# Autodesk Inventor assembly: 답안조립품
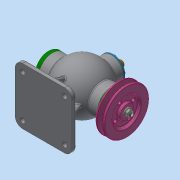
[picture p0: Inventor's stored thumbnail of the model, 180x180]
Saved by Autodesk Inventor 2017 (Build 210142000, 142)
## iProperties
Part Number: 답안조립품
Material: 일반
Document SubType Name: Assembly
Designer: MRC
Author: MRC
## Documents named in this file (16)
- C:\Users\MRC\Desktop\720811V1001\답안조립품.iam
- C:\Users\MRC\Desktop\720811V1001\본체.ipt
- C:\Users\MRC\Desktop\720811V1001\V-벨트풀리.ipt
- C:\Users\MRC\Desktop\720811V1001\너트 M8.ipt
- C:\Users\MRC\Desktop\720811V1001\뒤커버.ipt
- C:\Users\MRC\Desktop\720811V1001\베어링- 6202.ipt
- KS B 2023 - 6202 - 15 x 35 x 11 - 7.8.ipt
- C:\Users\MRC\Desktop\720811V1001\볼트 M4 x 12.ipt
- C:\Users\MRC\Desktop\720811V1001\볼트 M4 x 16.ipt
- C:\Users\MRC\Desktop\720811V1001\상부커버.ipt
- C:\Users\MRC\Desktop\720811V1001\슬라이드.ipt
- C:\Users\MRC\Desktop\720811V1001\앞커버.ipt
- C:\Users\MRC\Desktop\720811V1001\오일실 15 30 7.ipt
- C:\Users\MRC\Desktop\720811V1001\칼라.ipt
- C:\Users\MRC\Desktop\720811V1001\키 4 x 4 x 12.ipt
- C:\Users\MRC\Desktop\720811V1001\편심축.ipt
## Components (15 placed, 4 different names)
1. V-벨트풀리:1
2. KS B 2023 - 6202 - 15 x 35 x 11 - 7.8:1
3. KS B 2023 - 6202 - 15 x 35 x 11 - 7.8:2
4. KS B 1021 - 에 따름 ISO 1207 - 미터 A  M 4 x 12:1
5. KS B 1021 - 에 따름 ISO 1207 - 미터 A  M 4 x 12:2
6. KS B 1021 - 에 따름 ISO 1207 - 미터 A  M 4 x 12:3
7. KS B 1021 - 에 따름 ISO 1207 - 미터 A  M 4 x 12:4
8. ISO 4762 M4 x 16:2
9. ISO 4762 M4 x 16:3
10. ISO 4762 M4 x 16:4
11. ISO 4762 M4 x 16:5
12. ISO 4762 M4 x 16:1
13. ISO 4762 M4 x 16:6
14. ISO 4762 M4 x 16:7
15. ISO 4762 M4 x 16:8
